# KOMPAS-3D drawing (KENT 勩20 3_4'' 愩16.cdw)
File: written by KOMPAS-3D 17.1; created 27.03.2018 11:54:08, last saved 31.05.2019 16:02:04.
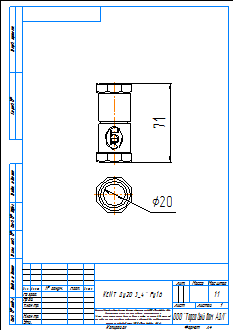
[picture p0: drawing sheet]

Sheet 1: A4, portrait

Title block, sheet 1: name: KENT Ду20 3_4'' Ру16; material: Внимание! Данный продукт является объектом авторского права ООО «Торговый Дом АДЛ». / Запрещается изменение, копирование, распространение / (в том числе путем копирования на другие сайты и ресурсы в Интернете) / или любое иное использование информации и объектов без предварительного / согласия правообладателя (ООО «Торговый Дом АДЛ»).; sheets: 1; organisation: ООО "Торговый дом АДЛ"; sheet format: A4; stored path: \\adlc.lan\data\АДЛ_ПКД\3D-модели\Поставщики\Standard Hidraulica\Латунный обратный клапан KENT PN16\KOMPAS 2D\KENT Ду20 3_4'' Ру16.cdw

Views: Вид 1, Проекционный вид 2
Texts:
  kka
  adl
Dimensions and other numbers on the sheet: 71; 20; 1:1; 1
